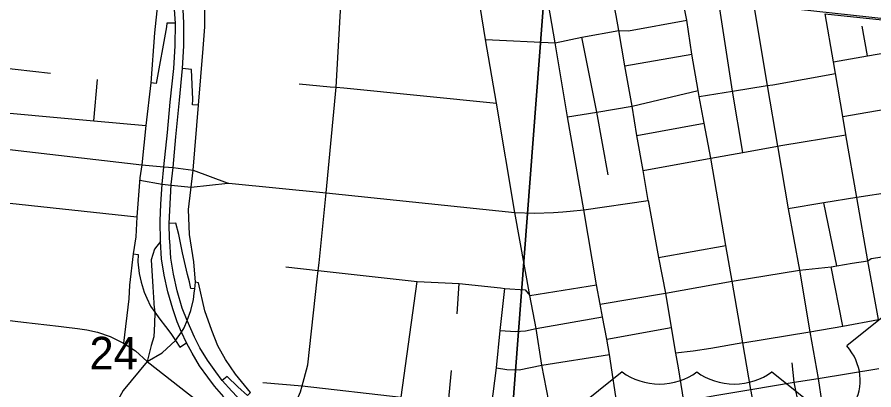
# Model space of a CAD drawing. Extents: x -8.2 to 38.5, y -0.1 to 21.9.
# Drawn here: x 5.851 to 6.953, y 14.446 to 14.926 of the extents above; entities that cross this region are included whole.
import ezdxf

# ---------------------------------------------------------------- set-up
doc = ezdxf.new("R2010")
doc.units = 0
for name, color, linetype in [('Default', 7, 'Continuous'), ('GM_X_Adjacent_County_Text', 7, 'Continuous'), ('GM_X_Airport_Location_Class_3', 7, 'Continuous'), ('GM_X_County_Road_Text', 7, 'Continuous'), ('GM_X_Interstate_Location', 7, 'Continuous'), ('GM_X_State_Location', 7, 'Continuous'), ('GM_X_Township_Subdivision', 7, 'Continuous'), ('GM_X_Township_Subdivision_Text', 7, 'Continuous'), ('GM_X_Township_Text', 7, 'Continuous')]:
    doc.layers.add(name, color=color, linetype=linetype)

msp = doc.modelspace()

# ---------------------------------------------------------------- linework, layer by layer
at = {"layer": 'Default'}
for points in [[(6.3184, 13.9645), (6.4535, 13.9645), (6.5306, 14.9717), (5.5208, 15.0744), (5.4096, 14.1041), (5.4716, 14.0826), (5.5242, 14.0651), (5.5618, 14.0529)], [(6.4535, 13.9645), (7.4558, 13.9645), (7.5202, 14.8634), (6.5306, 14.9717)]]:
    msp.add_lwpolyline(points, close=True, dxfattribs=at)
at = {"layer": 'GM_X_Adjacent_County_Text'}
msp.add_lwpolyline([(7.66, 15.8712), (7.5202, 14.8634), (6.5306, 14.9717), (6.65, 15.9814)], close=True, dxfattribs=at)
at = {"layer": 'GM_X_Airport_Location_Class_3'}
for p, q in [((6.6331, 14.8634), (6.6252, 14.9086)), ((6.6424, 14.8114), (6.6331, 14.8634)), ((6.6486, 14.7737), (6.6424, 14.8114)), ((6.6564, 14.7285), (6.6486, 14.7737)), ((6.663, 14.6899), (6.6564, 14.7285)), ((6.5804, 14.6781), (6.663, 14.6899)), ((6.663, 14.6899), (6.6761, 14.6168)), ((6.5964, 14.5814), (6.5804, 14.6781)), ((6.6761, 14.6168), (6.6853, 14.5708)), ((6.6011, 14.5565), (6.5964, 14.5814)), ((6.6853, 14.5708), (6.6924, 14.5263)), ((6.6041, 14.5404), (6.6011, 14.5565)), ((6.6099, 14.5115), (6.6041, 14.5404)), ((6.8711, 14.5209), (6.9135, 14.5282)), ((6.9135, 14.5282), (6.9595, 14.537)), ((6.6924, 14.5263), (6.6981, 14.4934)), ((6.7846, 14.5066), (6.8711, 14.5209)), ((6.6133, 14.4916), (6.6099, 14.5115)), ((6.6247, 14.4171), (6.6133, 14.4916))]:
    msp.add_line(p, q, dxfattribs=at)
for points in [[(6.6252, 14.9086), (6.6219, 14.9281), (6.615, 14.9635)], [(6.7846, 14.5066), (6.7435, 14.4995), (6.7209, 14.4962), (6.6981, 14.4934)], [(6.8068, 14.381), (6.8017, 14.4126), (6.7952, 14.4467), (6.7846, 14.5066)], [(6.6981, 14.4934), (6.7014, 14.4745), (6.7051, 14.4533), (6.7083, 14.4318)]]:
    msp.add_lwpolyline(points, dxfattribs=at)
at = {"layer": 'GM_X_Interstate_Location'}
for points in [[(6.0547, 14.9181), (6.0437, 14.9181), (6.0431, 14.9135), (6.0301, 14.8407), (6.023, 14.8416)], [(6.0844, 14.8127), (6.0768, 14.8132), (6.077, 14.82), (6.0755, 14.8586), (6.064, 14.86)], [(6.0796, 14.5764), (6.0744, 14.5767), (6.0728, 14.5854), (6.0704, 14.5949), (6.0639, 14.6227), (6.059, 14.6463), (6.0553, 14.6608), (6.0466, 14.6605)], [(6.0002, 14.6212), (6.0068, 14.6205), (6.0066, 14.6108), (6.0081, 14.5959), (6.0107, 14.5848), (6.0146, 14.572), (6.0179, 14.5643), (6.0229, 14.5539), (6.0283, 14.5462), (6.0347, 14.5371), (6.0421, 14.5277), (6.0489, 14.5186), (6.0548, 14.5096), (6.0605, 14.501), (6.069, 14.5068)], [(6.1513, 14.4428), (6.132, 14.4665), (6.119, 14.4854), (6.1093, 14.5031), (6.1018, 14.5228), (6.0928, 14.5478), (6.0845, 14.5841), (6.0807, 14.5847)], [(6.1513, 14.4428), (6.1475, 14.4388), (6.1351, 14.45), (6.1213, 14.4634), (6.1151, 14.4582)]]:
    msp.add_lwpolyline(points, dxfattribs=at)
at = {"layer": 'GM_X_State_Location'}
for points in [[(6.0473, 14.6402), (6.0466, 14.6605), (6.0493, 14.7104), (6.0517, 14.7326), (6.0555, 14.7719), (6.0602, 14.8193), (6.064, 14.86), (6.0655, 14.889), (6.0657, 14.9182), (6.0638, 14.954), (6.058, 14.9855), (6.053, 15.0066), (6.0497, 15.0186), (6.0409, 15.045), (6.03, 15.0709), (6.0168, 15.0974), (5.9785, 15.1664)], [(6.117, 14.4373), (6.1049, 14.4511), (6.0964, 14.4624), (6.0857, 14.4773), (6.0761, 14.4933), (6.069, 14.5068), (6.0625, 14.5204), (6.0571, 14.5338), (6.0515, 14.5504), (6.045, 14.5725), (6.0403, 14.594), (6.037, 14.6147), (6.0355, 14.637), (6.0353, 14.6638), (6.0358, 14.6853), (6.0375, 14.7111), (6.0398, 14.7335), (6.0444, 14.7776), (6.0482, 14.8165), (6.0529, 14.8599), (6.0545, 14.889), (6.0547, 14.9181), (6.0522, 14.9543)], [(6.2084, 14.3765), (6.2, 14.3821), (6.1918, 14.3876), (6.1755, 14.3999), (6.156, 14.4155), (6.1406, 14.4303), (6.1272, 14.4444), (6.1151, 14.4582), (6.1066, 14.4695), (6.096, 14.4844), (6.0863, 14.5004), (6.0792, 14.5139), (6.0697, 14.5354), (6.0634, 14.5515), (6.057, 14.5736), (6.0522, 14.5951), (6.0489, 14.6158), (6.0474, 14.6381), (6.0473, 14.6402)]]:
    msp.add_lwpolyline(points, dxfattribs=at)
at = {"layer": 'GM_X_Township_Subdivision'}
for p, q in [((6.9871, 14.5578), (6.9184, 14.5028)), ((6.6296, 14.4694), (6.5609, 14.4145)), ((6.8905, 14.4145), (6.8218, 14.4694))]:
    msp.add_line(p, q, dxfattribs=at)
for centre, major_axis, start_param, end_param in [((6.8397, 14.4587), (0.0961, 0), 5.838949, 6.894067), ((6.6776, 14.5087), (-0.0687, 0), 0.795399, 2.346194), ((6.7738, 14.5087), (-0.0687, 0), 0.795399, 2.346194)]:
    msp.add_ellipse(centre, major_axis=major_axis, ratio=0.8, start_param=start_param, end_param=end_param, dxfattribs=at)
at = {"layer": 'GM_X_Township_Subdivision_Text'}
for p, q in [((6.9451, 14.876), (6.9382, 14.9145)), ((6.6331, 14.8634), (6.719, 14.8784)), ((5.801, 14.8642), (5.8939, 14.8537)), ((5.9499, 14.7926), (5.9547, 14.8455)), ((6.2715, 14.8348), (6.468, 14.8153)), ((6.6486, 14.7737), (6.7351, 14.7895)), ((5.7812, 14.693), (6.0051, 14.6691)), ((6.9056, 14.6057), (6.8892, 14.6869)), ((6.6761, 14.6168), (6.763, 14.632)), ((6.9135, 14.5282), (6.8986, 14.6045)), ((6.4172, 14.5439), (6.4197, 14.583)), ((6.6099, 14.5115), (6.6924, 14.5263)), ((6.4062, 14.4304), (6.41, 14.4712))]:
    msp.add_line(p, q, dxfattribs=at)
for points in [[(6.5804, 14.6781), (6.5593, 14.7975), (6.5434, 14.8929), (6.537, 14.9301), (6.5298, 14.9722), (6.5232, 15.0158), (6.5165, 15.0544), (6.5081, 15.1028), (6.501, 15.1435), (6.4896, 15.1961), (6.4846, 15.2192), (6.4719, 15.3023), (6.4688, 15.3169), (6.4658, 15.3278), (6.4599, 15.3422), (6.4523, 15.3555), (6.4444, 15.3656), (6.4285, 15.3873), (6.4165, 15.4021), (6.4079, 15.4063), (6.3994, 15.4078), (6.3833, 15.405)], [(6.7849, 14.7517), (6.7716, 14.8307), (6.7534, 14.9479), (6.7409, 15.0202), (6.7255, 15.1052)], [(6.4537, 14.8973), (6.5434, 14.8929), (6.5776, 14.9001), (6.6252, 14.9086), (6.6378, 14.9084), (6.7128, 14.9219)], [(6.6114, 14.723), (6.5969, 14.8038), (6.5776, 14.9001)], [(6.9013, 14.8686), (6.9451, 14.876), (6.9878, 14.8836)], [(6.7286, 14.8238), (6.7716, 14.8307), (6.816, 14.8378), (6.8232, 14.8389), (6.904, 14.8534)], [(6.2138, 14.8403), (6.2539, 14.8364), (6.2617, 14.8357), (6.2715, 14.8348)], [(6.5593, 14.7975), (6.5969, 14.8038), (6.6424, 14.8114), (6.7273, 14.8315)], [(6.9133, 14.7982), (7, 14.8131), (7.0448, 14.8203), (7.0856, 14.8268)], [(5.6984, 14.815), (5.7896, 14.8069), (5.7943, 14.8065), (5.9499, 14.7926), (6.0167, 14.7864)], [(5.791, 14.7779), (5.8152, 14.7584), (6.0115, 14.7358)], [(6.6564, 14.7285), (6.7436, 14.7443), (6.7849, 14.7517), (6.8294, 14.7598), (6.8338, 14.7606), (6.9174, 14.7744)], [(6.1967, 14.6044), (6.2386, 14.5997), (6.3657, 14.5855), (6.4197, 14.583), (6.4731, 14.5776), (6.4787, 14.5769), (6.5049, 14.5749), (6.5106, 14.5678), (6.5964, 14.5814)], [(6.3463, 14.3793), (6.3419, 14.384), (6.3401, 14.3869), (6.3398, 14.3884), (6.3453, 14.4369), (6.3657, 14.5855)], [(6.4505, 14.3093), (6.4555, 14.3632), (6.4613, 14.4245), (6.4677, 14.4747), (6.4727, 14.5228), (6.4787, 14.5769)], [(6.4727, 14.5228), (6.4921, 14.5212), (6.5053, 14.5223), (6.5189, 14.525), (6.6041, 14.5404)], [(6.4677, 14.4747), (6.4813, 14.4724), (6.4972, 14.4722), (6.5263, 14.4779), (6.6133, 14.4916)], [(6.8627, 14.3923), (6.8573, 14.4244), (6.851, 14.4561), (6.8483, 14.481)], [(6.1671, 14.4559), (6.2179, 14.4512), (6.3453, 14.4369), (6.3609, 14.4352), (6.4062, 14.4304), (6.4613, 14.4245), (6.5037, 14.4199), (6.5382, 14.4162), (6.575, 14.4123), (6.5826, 14.4123), (6.5896, 14.4127), (6.5982, 14.4137), (6.6082, 14.415), (6.6247, 14.4171)]]:
    msp.add_lwpolyline(points, dxfattribs=at)
at = {"layer": 'GM_X_Township_Text'}
for p, q in [((6.0774, 14.729), (6.0844, 14.8127)), ((6.0796, 14.5764), (6.0807, 14.5847))]:
    msp.add_line(p, q, dxfattribs=at)
for points in [[(6.2397, 14.6097), (6.2488, 14.6998), (6.2617, 14.8357), (6.2707, 14.9955), (6.2755, 15.0416), (6.2798, 15.0832), (6.2842, 15.1256), (6.2881, 15.1669), (6.2927, 15.2057), (6.296, 15.2385), (6.3001, 15.2743), (6.3042, 15.3102), (6.3068, 15.3233), (6.3094, 15.3292), (6.3124, 15.3348), (6.3168, 15.3406), (6.3214, 15.3454), (6.3341, 15.3579)], [(6.7846, 14.5066), (6.7709, 14.586), (6.763, 14.632), (6.7436, 14.7443), (6.7351, 14.7895), (6.7286, 14.8238), (6.7273, 14.8315), (6.719, 14.8784), (6.7128, 14.9219), (6.7067, 14.953), (6.6953, 15.0118), (6.6929, 15.0266), (6.6818, 15.0963), (6.6803, 15.1043), (6.6677, 15.1768), (6.6547, 15.2516), (6.6517, 15.2689), (6.6356, 15.3611)], [(6.7334, 15.3135), (6.7394, 15.2837), (6.755, 15.192), (6.7687, 15.1125), (6.7713, 15.0977), (6.7835, 15.0268), (6.7984, 14.9433), (6.816, 14.8378), (6.8294, 14.7598), (6.8298, 14.7577), (6.843, 14.6793), (6.8577, 14.6004), (6.8711, 14.5209), (6.8816, 14.461), (6.8864, 14.4293), (6.8921, 14.3974), (6.9014, 14.3464), (6.912, 14.2821), (6.9207, 14.2363), (6.9281, 14.1944), (6.9423, 14.1078), (6.9586, 14.0221)], [(6.0844, 14.8127), (6.0904, 14.8856), (6.0928, 14.9134), (6.0926, 14.9413), (6.0897, 14.968), (6.0781, 15.0158)], [(6.4915, 14.6746), (6.468, 14.8153), (6.4537, 14.8973), (6.4467, 14.9396), (6.4404, 14.9783)], [(6.0316, 14.9424), (6.0277, 14.9056), (6.023, 14.8416)], [(6.9595, 14.537), (6.9454, 14.6124), (6.9314, 14.6938), (6.9174, 14.7744), (6.9133, 14.7982), (6.904, 14.8534), (6.9013, 14.8686), (6.8905, 14.9304)], [(6.8905, 14.9304), (6.9354, 14.9253), (6.9806, 14.9206), (7.0731, 14.9112), (7.1154, 14.9071), (7.1585, 14.9025), (7.2116, 14.8976), (7.2203, 14.8966), (7.2408, 14.8934), (7.2624, 14.8879), (7.353, 14.8579), (7.544, 14.7989)], [(6.023, 14.8416), (6.0167, 14.7864), (6.0115, 14.7358), (6.009, 14.7192), (6.0051, 14.6691), (6.0037, 14.6434), (6.0002, 14.6212)], [(6.0115, 14.7358), (6.0398, 14.7335), (6.0517, 14.7326), (6.0774, 14.729), (6.1214, 14.7127), (6.1223, 14.7123), (6.1233, 14.7122)], [(6.0807, 14.5847), (6.0785, 14.6111), (6.0729, 14.6463), (6.0717, 14.6783), (6.0774, 14.729)], [(6.0088, 14.7161), (6.0375, 14.7111), (6.0492, 14.7097), (6.0749, 14.7071), (6.1223, 14.7123)], [(7.1048, 14.7239), (7.0613, 14.717), (7.0233, 14.7101), (7.0184, 14.7082), (6.9763, 14.7006), (6.9314, 14.6938)], [(6.1233, 14.7122), (6.2488, 14.6998), (6.4915, 14.6746), (6.5168, 14.6735), (6.541, 14.6746), (6.5532, 14.6753), (6.5627, 14.6763), (6.5804, 14.6781)], [(6.9314, 14.6938), (6.8892, 14.6869), (6.843, 14.6793)], [(6.5189, 14.525), (6.5106, 14.5678), (6.4915, 14.6746)], [(6.9255, 14.6091), (6.9454, 14.6124), (6.95, 14.6151), (6.9893, 14.6215), (7.0324, 14.6284), (7.0752, 14.6358), (7.1205, 14.6429)], [(6.0355, 14.637), (6.0277, 14.6275), (6.0235, 14.6135), (6.0257, 14.5788), (6.027, 14.5583), (6.0272, 14.5561)], [(6.0002, 14.6212), (5.9956, 14.5808), (5.9947, 14.5632), (5.9881, 14.5065)], [(6.2205, 14.461), (6.225, 14.4785), (6.2373, 14.5886), (6.2386, 14.5997), (6.2397, 14.6097)], [(6.6011, 14.5565), (6.6853, 14.5708), (6.7709, 14.586), (6.8577, 14.6004), (6.8986, 14.6045), (6.9056, 14.6057), (6.9255, 14.6091)], [(6.0184, 14.4828), (6.0379, 14.4937), (6.0548, 14.5096), (6.0625, 14.5204), (6.0658, 14.5262), (6.0697, 14.5354), (6.0744, 14.5485), (6.078, 14.5627), (6.0789, 14.5707), (6.0796, 14.5764)], [(6.0272, 14.5561), (6.0283, 14.5462), (6.0277, 14.531), (6.0269, 14.5145), (6.0235, 14.5034), (6.0184, 14.4828)], [(5.7808, 14.5427), (5.8595, 14.5334), (5.9044, 14.5282), (5.9113, 14.5274)], [(5.9113, 14.5274), (5.9289, 14.5253), (5.941, 14.5236), (5.9546, 14.5204), (5.9706, 14.5151), (5.9881, 14.5065)], [(6.5382, 14.4162), (6.5263, 14.4779), (6.5189, 14.525)], [(5.9881, 14.5065), (6.0036, 14.4965), (6.0184, 14.4828)], [(6.0184, 14.4828), (5.9876, 14.4456), (5.9684, 14.4106), (5.9622, 14.3866), (5.9575, 14.3643), (5.9556, 14.3218)], [(6.0184, 14.4828), (6.1781, 14.3577), (6.2488, 14.3104), (6.2675, 14.2978)], [(6.6247, 14.4171), (6.7083, 14.4318), (6.7515, 14.4392), (6.7952, 14.4467), (6.851, 14.4561), (6.8816, 14.461), (6.9598, 14.4736)], [(6.1909, 14.3856), (6.1918, 14.3876), (6.1997, 14.4054), (6.2076, 14.4247), (6.2156, 14.4436), (6.2179, 14.4512), (6.2205, 14.461)]]:
    msp.add_lwpolyline(points, dxfattribs=at)

# ---------------------------------------------------------------- texts
at = {"layer": 'GM_X_County_Road_Text'}
msp.add_text('24', height=0.04186, rotation=0, dxfattribs=at).set_placement((5.9442, 14.4726))

doc.saveas('drawing.dxf')
